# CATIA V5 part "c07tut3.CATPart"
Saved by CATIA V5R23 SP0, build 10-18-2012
Part number: Part1
Bounding box of the stored display mesh (mm): x 0 to 108, y -53 to 53, z -53 to 53
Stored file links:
  D:\APS\CATIA V5-6R-2013-Project\CATIA V5-6R2013_partfiles\Tutorials\c07_catia_v5-6r2013_tut\c07tut3.CATPart
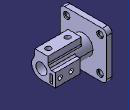
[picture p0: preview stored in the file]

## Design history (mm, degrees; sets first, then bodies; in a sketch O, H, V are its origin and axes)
Body1 (main body)
  Sketch1 on yz-plane, origin (0, 0, 0), H (0, 1, 0), V (0, 0, 1)
    line L1 (53, 43) -> (53, -43)
    line L2 (43, -53) -> (-43, -53)
    line L3 (-53, -43) -> (-53, 43)
    line L4 (-43, 53) -> (43, 53)
    point P1 (53, 53)
    point P2 (53, -53)
    point P3 (-53, -53)
    arc A1 centre (43, 43) radius 10 from (53, 43) to (43, 53) ccw
    arc A2 centre (43, -43) radius 10 from (53, -43) to (43, -53) cw
    arc A3 centre (-43, -43) radius 10 from (-43, -53) to (-53, -43) cw
    arc A4 centre (-43, 43) radius 10 from (-53, 43) to (-43, 53) cw
    distance P1 P2 = 106
    radius A1 = 10
    distance P2 P3 = 106
    radius A2 = 10
    radius A3 = 10
    radius A4 = 10
    vertical: L1 V, L3 V
    horizontal: L2 H, L4 H
    equidistance: L1 L3 O, L2 L4 O
    coincidence: L1 P1, L4 P1, L1 P2, L2 P2, L2 P3, L3 P3
    tangency: A1 L1, A1 L4, A2 L1, A2 L2, A3 L2, A3 L3, A4 L3, A4 L4
  Pad1: profile Sketch1, direction (1, 0, 0), length 12
  Sketch2 on face of Pad1, origin (12, 0, 0), H (0, 1, 0), V (0, 0, 1)
    circle A1 centre (0, 0) radius 22
    radius A1 = 22
  Pad2: profile Sketch2, direction (1, 0, 0), length 96
  Sketch3 on face of Pad2, origin (108, 0, 0), H (0, 1, 0), V (0, 0, 1)
    point P1 (-15, 16.0935)
    line L1 (-15, 16.0935) -> (-15, 32)
    line L2 (-15, 32) -> (15, 32)
    line L3 (15, 32) -> (15, 16.0935)
    point P4 (15, 16.0935)
    axis line L4 (0, 0) -> (0, 32)
    point P5 (0, 32)
    reference projected circle E1 centre (0, 0) radius 22 from edge [face of Pad2 | face of Pad2]
    reference projected circle E2 centre (0, 0) radius 22 from edge [face of Pad2 | face of Pad2]
    projected circle E3 centre (0, 0) radius 22 from edge [face of Pad2 | face of Pad2]
    projected arc E4 centre (0, 0) radius 22 from (15, 16.0935) to (-15, 16.0935) ccw from edge [face of Pad2 | face of Pad2]
    length L2 = 30
    distance H L2 = 32
    vertical: L1 V, L3 V, L4 V
    horizontal: L2 H
    midpoint: P5 L2
    coincidence: P4 E1, P1 E2
  Pad3: profile Sketch3, direction (-1, 0, 0), length 76
  Sketch4 on face of Pad2, origin (108, 0, 0), H (0, 1, 0), V (0, 0, 1)
    point P1 (0, -22)
    line L1 (0, -22) -> (32, -22)
    line L2 (32, -22) -> (32, 8)
    line L3 (32, 8) -> (20.4939, 8)
    point P4 (20.4939, 8)
    reference projected circle E1 centre (0, 0) radius 22 from edge of Pad2
    reference projected circle E2 centre (0, 0) radius 22 from edge [face of Pad2 | face of Pad2]
    reference projected circle E3 centre (0, 0) radius 22 from edge [face of Pad2 | face of Pad2]
    projected arc E4 centre (0, 0) radius 22 from (-15, 16.0935) to (15, 16.0935) ccw from edge of Pad3
    projected arc E5 centre (0, 0) radius 22 from (0, -22) to (20.4939, 8) ccw from edge of Pad3
    length L2 = 30
    distance V L2 = 32
    coincidence: P1 V, P4 E1, P1 E2
    horizontal: L1 H, L3 H
    vertical: L2 V
    tangency: L1 E3
  Pad4: profile Sketch4, direction (-1, 0, 0), length 57
  Sketch5 on face of Pad2, origin (108, 0, 0), H (0, 1, 0), V (0, 0, 1)
    line L1 (19, 1) -> (25, 1)
    line L2 (25, 1) -> (25, -18)
    line L3 (25, -18) -> (19, -18)
    line L4 (19, -18) -> (19, 1)
    reference projected line E1 (53, -43) -> (53, 43) from edge [face of Pad1 | face of Pad1]
    reference projected line E2 (-43, -53) -> (43, -53) from edge [face of Pad1 | face of Pad1]
    length L3 = 6
    length L2 = 19
    distance L4 E1 = 34
    distance L3 E2 = 35
    horizontal: L1 H, L3 H
    vertical: L2 V, L4 V
  Pocket1: profile Sketch5, direction (-1, 0, 0), length 50
  Sketch6 on face of Pad2, origin (108, 0, 0), H (0, 1, 0), V (0, 0, 1)
    point P1 (0, 0)
    coincidence: P1 O
  Hole1: placed by Sketch6, at (108, 0, 0) direction (-1, 0, 0), diameter 25, depth 82, V-bottom angle 120
  Sketch7 on face of Pad3, origin (90.7325, -5.9449, 32), H (1, 0, 0), V (0, 1, 0)
    point P1 (1.2675, 5.9449)
    reference projected line E1 (17.2675, -9.0551) -> (-58.7325, -9.0551) from edge [face of Pad3 | face of Pad3]
    reference projected line E2 (17.2675, 20.9449) -> (17.2675, -9.0551) from edge [face of Pad3 | face of Pad3]
    distance P1 E1 = 15
    distance P1 E2 = 16
  Hole2: placed by Sketch7, at (92, 0, 32) direction (0, 0, -1), diameter 12, depth 33.0037, threaded, thread diameter 13.2, thread depth 10, pitch 1
  RectPattern1: of Hole2, direction 1 instances 2, spacing 44, along edge [face of Pad3 | face of Pad3]
  Sketch8 on face of Pad4, origin (86.2721, 32, -2.7131), H (1, 0, 0), V (0, 0, -1)
    point P1 (10.7279, 4.2869)
    reference projected line E1 (21.7279, 19.2869) -> (-35.2721, 19.2869) from edge [face of Pad4 | face of Pad4]
    reference projected line E2 (21.7279, 19.2869) -> (21.7279, -10.7131) from edge [face of Pad4 | face of Pad4]
    distance P1 E1 = 15
    distance E2 P1 = 11
  Hole3: placed by Sketch8, at (97, 32, -7) direction (0, -1, 0), diameter 10, through (limit type 6), threaded, thread diameter 11, thread depth 7.5, pitch 1
  RectPattern2: of Hole3, direction 1 instances 2, spacing 25, along edge [face of Pad4 | face of Pad4], direction 2 instances 2, spacing 76
  Sketch9 on face of Pad1, origin (12, -36.1764, 22.8739), H (0, 1, 0), V (0, 0, 1)
    point P1 (-1.8236, -60.8739)
    reference projected line E1 (-16.8236, 20.1261) -> (-16.8236, -65.8739) from edge [face of Pad1 | face of Pad1]
    reference projected line E2 (-6.8236, -75.8739) -> (79.1764, -75.8739) from edge [face of Pad1 | face of Pad1]
    distance P1 E1 = 15
    distance E2 P1 = 15
  Hole4: placed by Sketch9, at (12, -38, -38) direction (-1, 0, 0), diameter 10, through (limit type 3), counterbore diameter 15, counterbore depth 3
  RectPattern3: of Hole4, direction 1 instances 2, spacing 76, along edge [face of Pad1 | face of Pad1], direction 2 instances 2, spacing 76, along edge [face of Pad1 | face of Pad1] reversed
  Fillet1: radius 15, on edge [face of Pad3 | face of Pad2]
  Fillet2: radius 5, on edge [face of Pad2 | face of Pad3]; edge [face of Pad2 | face of Pad4]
